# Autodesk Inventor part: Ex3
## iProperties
Author: Administrator
Created: 2001-01
Part Number: Ex3
Document SubType Name: Modeling
Designer: Administrator
Control State: 0
Master: False
Checked Out: False
PropertySet Name: Design Tracking Control
Shininess: 60.0
PropertySet Name: _Private Model Information
Density: 0.0
Volumn: 0.0
Area: 0.0
PropertySet Name: Model Information
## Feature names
1. Revolution1
2. Hole1
3. Circular Pattern1
4. Extrusion1
5. Fillet1
